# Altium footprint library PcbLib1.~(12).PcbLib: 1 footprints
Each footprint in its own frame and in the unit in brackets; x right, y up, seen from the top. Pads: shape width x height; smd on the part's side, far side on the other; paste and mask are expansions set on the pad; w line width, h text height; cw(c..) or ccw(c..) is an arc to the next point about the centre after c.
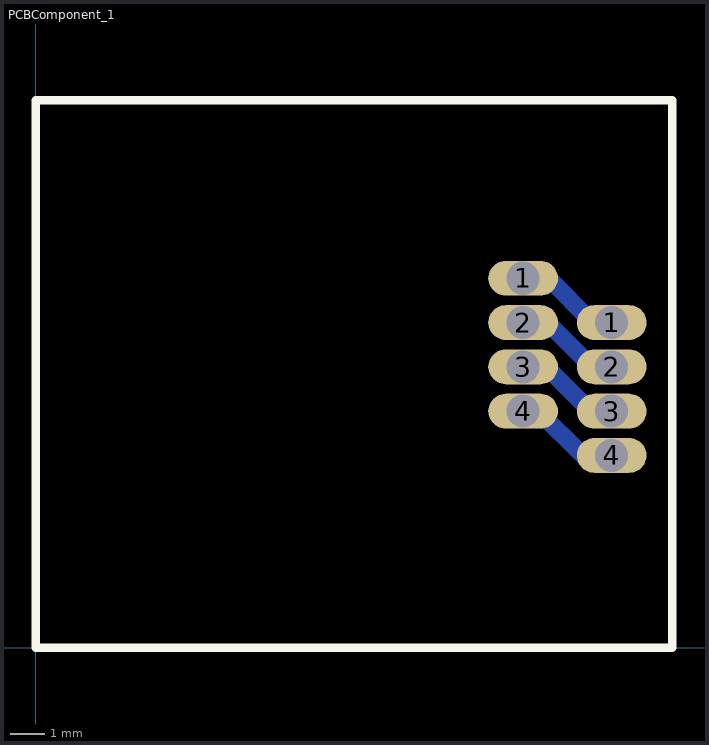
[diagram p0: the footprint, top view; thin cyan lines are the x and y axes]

## PCBComponent_1 [mm]
pads (8):
  oval 2x1 hole 0.95: 1(13.975,10.595) 1(16.515,9.325) 2(13.975,9.325) 2(16.515,8.055) 3(13.975,8.055) 3(16.515,6.785) 4(13.975,6.785) 4(16.515,5.515)
Bottom Layer:
  lines w0.5: 13.975,6.785 14.415,6.785 15.685,5.515 16.515,5.515 ; 13.975,8.055 14.645,8.055 15.915,6.785 16.515,6.785 ; 13.975,9.325 14.675,9.325 15.945,8.055 16.515,8.055 ; 13.975,10.595 14.705,10.595 15.975,9.325 16.515,9.325
Top Overlay:
  lines w0.254: 0,0 0,15.7 18.25,15.7 18.25,0 0,0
